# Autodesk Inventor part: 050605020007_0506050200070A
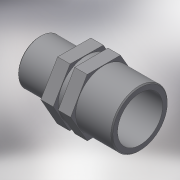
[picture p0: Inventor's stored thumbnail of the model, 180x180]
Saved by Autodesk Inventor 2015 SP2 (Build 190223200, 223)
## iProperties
Created: 2017-05
Part Number: 050605020007_0506050200070A
Material: Generic
Description: PLASSON REDUCING NIPPLE 2"-3/4"
Document SubType Name: Modeling
Designer: KIM
Density: 1 g/cm^3
Appearance: Default
Author: KIM
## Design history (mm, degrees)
derived "050605.ipt"
feature "Solid1::050605.ipt"
tag "TaggingFeature1"
body "Solid1"
other parameters: "d0" = 59, "d1" = 59.614, "d5" = 25, "d6" = 5.9, "d8" = 0.59, "d12" = 0, "d14" = 26.441, "d15" = 21.1528, "d16" = 47.6912, "d17" = 17, "d18" = 2.95, "d19" = 63, "d21" = 0, "H_" = 59, "R_" = 59.614, "E_" = 63, "l_" = 25, "R_1" = 26.441, "l_1" = 17
